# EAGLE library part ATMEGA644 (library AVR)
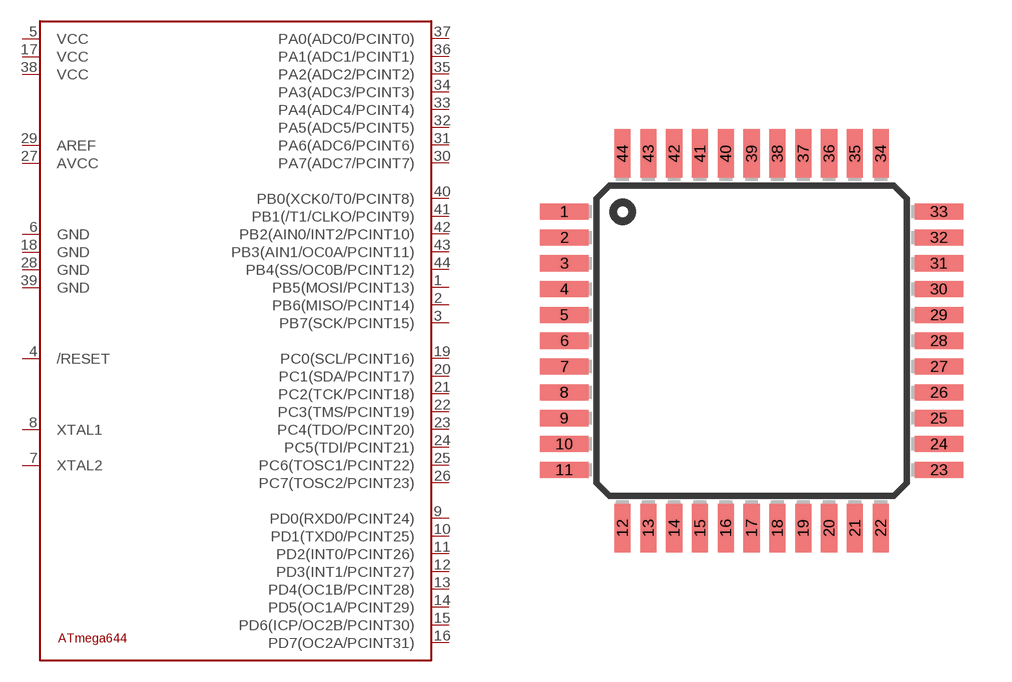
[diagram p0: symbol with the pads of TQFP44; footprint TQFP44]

Designator prefix U

## ATMEGA644  [TQFP44]
1  PB5(MOSI/PCINT13)
2  PB6(MISO/PCINT14)
3  PB7(SCK/PCINT15)
4  /RESET  in
5  VCC  pwr
6  GND  pwr
7  XTAL2  out
8  XTAL1  in
9  PD0(RXD0/PCINT24)
10  PD1(TXD0/PCINT25)
11  PD2(INT0/PCINT26)
12  PD3(INT1/PCINT27)
13  PD4(OC1B/PCINT28)
14  PD5(OC1A/PCINT29)
15  PD6(ICP/OC2B/PCINT30)
16  PD7(OC2A/PCINT31)
17  VCC  pwr
18  GND  pwr
19  PC0(SCL/PCINT16)
20  PC1(SDA/PCINT17)
21  PC2(TCK/PCINT18)
22  PC3(TMS/PCINT19)
23  PC4(TDO/PCINT20)
24  PC5(TDI/PCINT21)
25  PC6(TOSC1/PCINT22)
26  PC7(TOSC2/PCINT23)
27  AVCC  pwr
28  GND  pwr
29  AREF  pwr
30  PA7(ADC7/PCINT7)
31  PA6(ADC6/PCINT6)
32  PA5(ADC5/PCINT5)
33  PA4(ADC4/PCINT4)
34  PA3(ADC3/PCINT3)
35  PA2(ADC2/PCINT2)
36  PA1(ADC1/PCINT1)
37  PA0(ADC0/PCINT0)
38  VCC  pwr
39  GND  pwr
40  PB0(XCK0/T0/PCINT8)
41  PB1(/T1/CLKO/PCINT9)
42  PB2(AIN0/INT2/PCINT10)
43  PB3(AIN1/OC0A/PCINT11)
44  PB4(SS/OC0B/PCINT12)

## Footprint TQFP44 (pad centres in mm)
Thin Plasic Quad Flat Package
smd 1.5 x 0.5: 1 -5.8,4; 2 -5.8,3.2; 3 -5.8,2.4; 4 -5.8,1.6; 5 -5.8,0.8; 6 -5.8,0; 7 -5.8,-0.8; 8 -5.8,-1.6; 9 -5.8,-2.4; 10 -5.8,-3.2; 11 -5.8,-4; 23 5.8,-4; 24 5.8,-3.2; 25 5.8,-2.4; 26 5.8,-1.6; 27 5.8,-0.8; 28 5.8,0; 29 5.8,0.8; 30 5.8,1.6; 31 5.8,2.4; 32 5.8,3.2; 33 5.8,4
smd 0.5 x 1.5: 12 -4,-5.8; 13 -3.2,-5.8; 14 -2.4,-5.8; 15 -1.6,-5.8; 16 -0.8,-5.8; 17 0,-5.8; 18 0.8,-5.8; 19 1.6,-5.8; 20 2.4,-5.8; 21 3.2,-5.8; 22 4,-5.8; 34 4,5.8; 35 3.2,5.8; 36 2.4,5.8; 37 1.6,5.8; 38 0.8,5.8; 39 0,5.8; 40 -0.8,5.8; 41 -1.6,5.8; 42 -2.4,5.8; 43 -3.2,5.8; 44 -4,5.8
